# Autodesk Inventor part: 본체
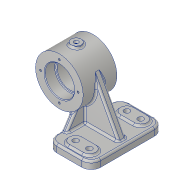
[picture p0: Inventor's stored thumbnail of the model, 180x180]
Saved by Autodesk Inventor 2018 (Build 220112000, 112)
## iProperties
Created: 2023-08
Part Number: 본체
Material: 알루미늄 6061
Document SubType Name: Modeling
Designer: home
Density: 2.7 g/cm^3
Appearance: 알루미늄 - 평지
Mass: 777.596 g
Surface Area: 536.873 cm^2
Volume: 287.998 cm^3
Author: home
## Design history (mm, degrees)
sketch "스케치3"
  geometry: L1 (-27, 0)-(27, 0); L2 (-27, 0)-(-27, 38); L3 (-27, 38)-(27, 38); L4 (27, 38)-(27, 0); L5 (-27, 23.5)-(-10, 23.5); L6 (-10, 23.5)-(-10, 20.5); L7 (-10, 20.5)-(10, 20.5); L8 (10, 20.5)-(10, 23.5); L9 (10, 23.5)-(27, 23.5); 2 further points
  constraints: 18 end point, 5 perpendicular, 4 point on line, 2 horizontal, 1 coincident, 1 midpoint, 1 vertical
  dimensions: "d1" = 54 distance of L1.start L1.end; "d2" = 76 diameter of L3 L1; "d3" = 17 distance of L5.end L5.start; "d4" = 17 distance of L8.end L9.end; "d5" = 41 diameter of L7 L1; "d6" = 47 diameter of L5 L1
revolve "회전1" sketch "스케치3" stored, may be unused: angle "d7" = 90 deg
node "작업 평면1"
sketch "스케치4"
  geometry: L1 (27, -38)-(-27, -38) reference; L2 (-58, 12)-(58, 12); L3 (58, 12)-(58, 82); L4 (58, 82)-(-58, 82); L5 (-58, 82)-(-58, 12); 1 further point
  constraints: 8 end point, 2 parallel, 1 horizontal, 1 perpendicular
  dimensions: "d9" = 116 distance of L4.end L3.end; "d10" = 70 distance of L3.end L2.end; "d11" = 120 distance between parallel lines of L4 L1; "d12" = 58 distance from line of point (0, 0) L5
extrude "돌출1" join sketch "스케치4" distance "d13" = 12; taper "d14" = 0 deg
node "작업 평면2"
sketch "스케치5"
  geometry: C1 r 8 at (0, 0); 1 further point
  constraints: 1 centre point, 1 coincident
  dimensions: "d16" = 16 diameter of C1
extrude "돌출2" join sketch "스케치5" stored distance "d17" = 12; taper "d18" = 0 deg
sketch "스케치6"
  geometry: C1 r 8 at (0, 0) reference; 1 further point
  constraints: 1 coincident
hole "구멍1" sketch "스케치6" at (0, 0) diameter "d19" = 5.188; stored, may be unused: countersink angle "d23" = 90 deg, drill point angle "d25" = 118 deg; dims "d20" = 12, "d21" = 7, "d22" = 4, "d24" = 16
sketch "스케치8"
  geometry: C1 r 23.5 at (0, 0) reference; C2 r 38 at (0, 0) reference; A1 r 30 centre (0, 0) between (0, 30) and (30, 0); 2 further points
  constraints: 4 point on circle, 2 horizontal alignment, 2 vertical alignment, 1 centre point, 1 coincident
  dimensions: "d30" = 60 diameter of A1
hole "구멍2" sketch "스케치8" at (0, 30), (30, 0), (0, -30), (-30, 0) diameter "d31" = 3.242; stored, may be unused: countersink angle "d35" = 90 deg, drill point angle "d37" = 118 deg; dims "d32" = 8, "d33" = 7, "d34" = 4, "d36" = 10
sketch "스케치9"
  geometry: L1 (41, -8)-(37.148, -8) reference; L2 (37.148, 8)-(41, 8) reference; L3 (41, 8)-(41, 3.5) reference; L4 (41, 3.5)-(37, 3.5) reference; L5 (37, 3.5)-(37, 2.594) reference; L6 (37, 2.594)-(20.335, 2.594) reference; L7 (20.335, -2.594)-(37, -2.594) reference; L8 (37, -2.594)-(37, -3.5) reference; L9 (37, -3.5)-(41, -3.5) reference; L10 (41, -3.5)-(41, -8) reference; L11 (-58, 12)-(-70, 12) reference; L12 (-70, 12)-(-70, 82) reference; L13 (-70, 82)-(-58, 82) reference; L14 (-58, 82)-(-58, 12) reference; L15 (17.882, 33.529)-(-58, 74); L16 (-58, 12)-(-36.056, 12); A1 r 38 centre (0, 0) between (37.148, 8) and (37.148, -8) reference; A2 r 20.5 centre (0, 0) between (20.335, 2.594) and (20.335, -2.594) reference; A3 r 38 centre (0, 0) between (17.882, 33.529) and (-36.056, 12); 1 further point
  constraints: 6 end point, 4 point on circle, 1 centre point, 1 coincident, 1 horizontal, 1 point on line, 1 tangent
  dimensions: "d38" = 8 distance of L13.end L15.end
extrude "돌출3" join sketch "스케치9" stored distance "d39" = 12; taper "d40" = 0 deg
sketch "스케치15"
  geometry: L1 (58, -12)-(-58, -12) reference; L2 (7.5, -12)-(-7.5, -12); L3 (-7.5, -12)-(-7.5, -20); L4 (-7.5, -20)-(7.5, -20); L5 (7.5, -20)-(7.5, -12); 1 further point
  constraints: 8 end point, 2 parallel, 1 horizontal, 1 perpendicular, 1 point on line
  dimensions: "d57" = 8 distance of L2.end L3.end; "d58" = 15 distance of L3.end L4.end; "d87" = 7.5 distance from line of point (0, 0) L5
extrude "돌출6" join sketch "스케치15" stored distance "d60" = 8; taper "d61" = 0 deg; dims "d9" = 116, "d10" = 70, "d11" = 120, "d12" = 58
sketch "스케치16"
  geometry: L1 (0, 0)-(0, 12) reference; L2 (48, 53.379)-(68, 53.379) reference; L3 (68, 53.379)-(68, 49.795) reference; L4 (68, 49.795)-(85, 49.795) reference; L5 (85, 49.795)-(85, 33.944) reference; L6 (85, 33.944)-(65.5, 33.944) reference; L7 (116, 12)-(116, 0) reference; L8 (116, 0)-(0, 0) reference; L9 (0, 0)-(0, 12) reference; L10 (0, 12)-(50.5, 12) reference; L11 (48, 49.795)-(48, 53.379) reference; L12 (31, 49.795)-(48, 49.795) reference; L13 (31, 33.944)-(31, 49.795) reference; L14 (50.5, 33.944)-(31, 33.944) reference; L15 (31, 106.056)-(85, 106.056) reference; L16 (85, 106.056)-(85, 90.205) reference; L17 (85, 90.205)-(68, 90.205) reference; L18 (68, 90.205)-(68, 86.621) reference; L19 (68, 86.621)-(48, 86.621) reference; L20 (48, 86.621)-(48, 90.205) reference; L21 (48, 90.205)-(31, 90.205) reference; L22 (31, 90.205)-(31, 106.056) reference; L23 (116, 12)-(0, 12) reference; L24 (36.251, 33.944)-(22, 12); L25 (65.5, 33.944)-(65.5, 12) reference; L26 (65.5, 12)-(116, 12) reference; L27 (50.5, 12)-(50.5, 33.944) reference; L28 (65.5, 33.944)-(50.5, 33.944) reference; 1 further point
  constraints: 2 end point, 2 point on line
  dimensions: "d63" = 22 distance of L24.end L1.end; "d64" = 33 deg angle of L24 L1
feature "리브2" sketch "스케치16" dims "d65" = 1, "d66" = 8, "d67" = 0, "d68" = 0, "d69" = 1, "d70" = 1
fillet "모깎기1" dims "d71" = 15
sketch "스케치17"
  geometry: L1 (-43, -82)-(43, -82) reference; L2 (-31, -40)-(-31, -62); L3 (-51, -40)-(-51, -62); A1 r 10 centre (-41, -62) between (-31, -62) and (-51, -62); A2 r 10 centre (-41, -40) between (-31, -40) and (-51, -40); 1 further point
  constraints: 4 end point, 4 point on circle, 2 centre point, 2 tangent, 2 vertical
  dimensions: "d72" = 20 diameter of A1; "d73" = 20 distance from line of L1 A1.centre; "d74" = 20 diameter of A2; "d75" = 22 distance of A1.centre A2.centre; "d76" = 41 horizontal distance of A1.centre point (0, 0); "d77" = 41 horizontal distance of point (0, 0) A2.centre
extrude "돌출7" join sketch "스케치17" distance "d78" = 3; taper "d79" = 0 deg
sketch "스케치18"
  geometry: C1 r 4.5 at (-41, -40); C2 r 4.5 at (-41, -62); A1 r 10 centre (-41, -62) between (-51, -62) and (-31, -62) reference; A2 r 10 centre (-41, -40) between (-31, -40) and (-51, -40) reference; 1 further point
  constraints: 2 centre point, 2 coincident
  dimensions: "d80" = 9 diameter of C1; "d81" = 9 diameter of C2
extrude "돌출8" cut sketch "스케치18" extent not by distance; stored distance "d82" = 3; taper "d83" = 0 deg
fillet "모깎기2" dims "d84" = 3
fillet "모깎기20" dims "d109" = 3
fillet "모깎기21" dims "d110" = 3
fillet "모깎기22" dims "d111" = 3
sketch "스케치19"
  geometry: L1 (0, 0)-(86, 0) reference; 2 further points
  constraints: 1 vertical alignment, 1 other
  dimensions: "d92" = 19 distance from line of point (43, 19) L1
feature "엠보싱1" sketch "스케치19" dims "d93" = 0.5, "d94" = 0
fillet "모깎기9" dims "d95" = 1
chamfer "모따기1" distance "d96" = 1; stored, may be unused: second distance "d97" = 2, angle "d98" = 45 deg
fillet "모깎기23" dims "d112" = 3
node "솔리드1"
mirror "미러1"
mirror "미러2"
mirror "미러3"
node "절단 모서리 투영2"
node "절단 모서리 투영3"
other parameters: "d15" = -111
